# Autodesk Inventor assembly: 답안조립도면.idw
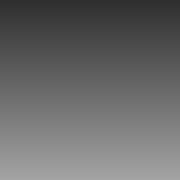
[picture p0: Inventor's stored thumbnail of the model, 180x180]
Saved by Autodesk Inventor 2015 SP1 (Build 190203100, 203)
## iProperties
Created: 2017-07
Part Number: 답안조립도면.idw
Document SubType Name: Assembly
Designer: C04
Author: C04
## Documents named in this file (1)
- C:\Users\C04\Desktop\470707V1009\답안조립도면.idw.iam
